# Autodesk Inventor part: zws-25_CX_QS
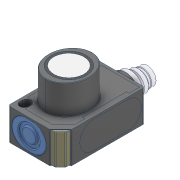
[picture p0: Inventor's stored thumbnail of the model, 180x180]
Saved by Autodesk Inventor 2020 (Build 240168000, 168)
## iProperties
Created: 2025-04
Part Number: zws-25_CX_QS
Material: Generisch
Description: STEP AP214
Document SubType Name: Modeling
Designer: Oliver Liedtke
Density: 1 g/cm^3
Appearance: Vorgabe
Title: zws-25_CX_QS.STEP
Revision Number: ANY
Sending System: SolidWorks 2024
Preprocessor: SwSTEP 2.0
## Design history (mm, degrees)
feature "Schnitt-Linear austragen1"
node "Volumenkörper1"
